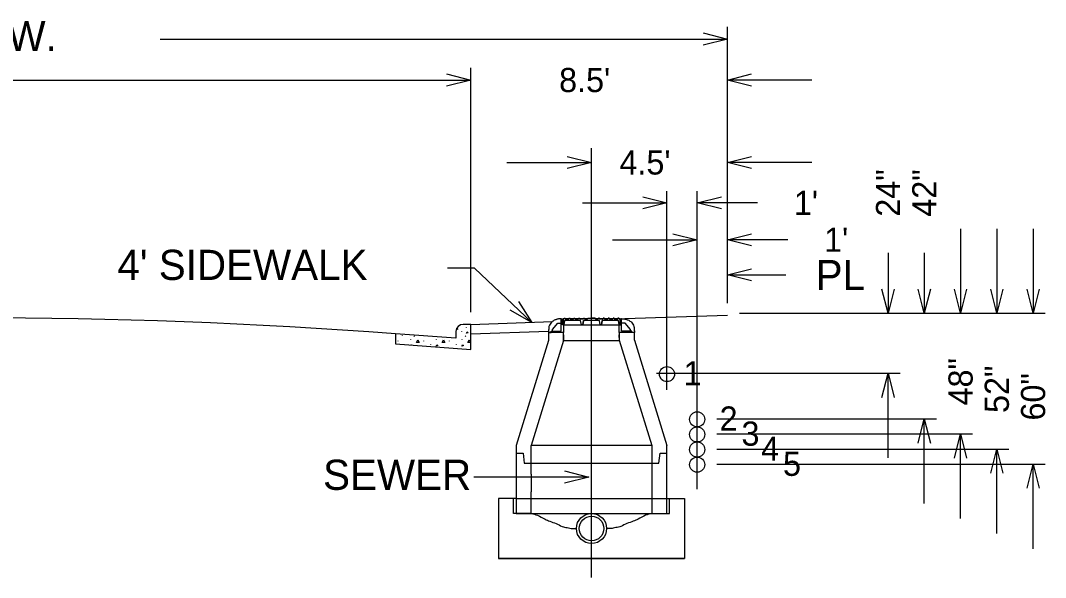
# Model space of a CAD drawing. Extents: x 524397 to 525117, y 3701341 to 3701821.
# Drawn here: x 524790.7 to 524858.6, y 3701583.9 to 3701620.9 of the extents above; entities that cross this region are included whole.
import ezdxf

# ---------------------------------------------------------------- set-up
doc = ezdxf.new("R2010")
doc.units = 0
doc.layers.add('Level 11', color=7, linetype='Continuous')

msp = doc.modelspace()

# ---------------------------------------------------------------- linework, layer by layer
at = {"layer": 'Level 11'}
for p, q in [((524835.918, 3701620.031), (524837.519, 3701619.631)), ((524837.519, 3701602.111), (524837.519, 3701620.431)), ((524799.959, 3701619.631), (524837.519, 3701619.631)), ((524837.519, 3701619.631), (524835.918, 3701619.23)), ((524818.923, 3701617.313), (524820.524, 3701616.913)), ((524818.923, 3701617.313), (524820.524, 3701616.913)), ((524820.524, 3701601.517), (524820.524, 3701617.714)), ((524837.519, 3701602.111), (524837.519, 3701617.714)), ((524837.519, 3701616.913), (524839.12, 3701617.313)), ((524790.181, 3701616.913), (524820.524, 3701616.913)), ((524814.921, 3701616.913), (524820.524, 3701616.913)), ((524820.524, 3701616.913), (524818.923, 3701616.513)), ((524820.524, 3701616.913), (524818.923, 3701616.513)), ((524843.123, 3701616.913), (524837.519, 3701616.913)), ((524839.12, 3701616.513), (524837.519, 3701616.913)), ((524828.519, 3701583.937), (524828.519, 3701612.406)), ((524826.918, 3701611.85), (524828.519, 3701611.45)), ((524837.519, 3701611.45), (524839.12, 3701611.85)), ((524822.916, 3701611.45), (524828.519, 3701611.45)), ((524828.519, 3701611.45), (524826.918, 3701611.05)), ((524843.123, 3701611.45), (524837.519, 3701611.45)), ((524839.12, 3701611.05), (524837.519, 3701611.45)), ((524831.918, 3701609.17), (524833.519, 3701608.77)), ((524833.519, 3701596.371), (524833.519, 3701609.547)), ((524835.519, 3701589.784), (524835.519, 3701609.547)), ((524835.519, 3701608.77), (524837.12, 3701609.17)), ((524827.916, 3701608.77), (524833.519, 3701608.77)), ((524833.519, 3701608.77), (524831.918, 3701608.37)), ((524839.522, 3701608.77), (524835.519, 3701608.77)), ((524837.12, 3701608.37), (524835.519, 3701608.77)), ((524852.962, 3701607.053), (524852.962, 3701601.45)), ((524855.363, 3701607.053), (524855.363, 3701601.45)), ((524857.765, 3701607.053), (524857.765, 3701601.45)), ((524829.916, 3701606.328), (524835.519, 3701606.328)), ((524833.918, 3701606.728), (524835.519, 3701606.328)), ((524835.519, 3701606.328), (524833.918, 3701605.928)), ((524837.519, 3701606.328), (524839.12, 3701606.728)), ((524841.522, 3701606.328), (524837.519, 3701606.328)), ((524839.12, 3701605.928), (524837.519, 3701606.328)), ((524848.159, 3701605.452), (524848.159, 3701601.45)), ((524850.561, 3701605.452), (524850.561, 3701601.45)), ((524820.782, 3701604.452), (524818.977, 3701604.452)), ((524824.56, 3701600.841), (524820.782, 3701604.452)), ((524837.519, 3701604.003), (524839.12, 3701604.403)), ((524837.519, 3701604.003), (524841.395, 3701604.003)), ((524839.12, 3701603.603), (524837.519, 3701604.003)), ((524848.159, 3701601.45), (524847.759, 3701603.051)), ((524848.559, 3701603.051), (524848.159, 3701601.45)), ((524850.561, 3701601.45), (524850.16, 3701603.051)), ((524850.961, 3701603.051), (524850.561, 3701601.45)), ((524852.962, 3701601.45), (524852.562, 3701603.051)), ((524853.362, 3701603.051), (524852.962, 3701601.45)), ((524855.363, 3701601.45), (524854.963, 3701603.051)), ((524855.764, 3701603.051), (524855.363, 3701601.45)), ((524857.765, 3701601.45), (524857.365, 3701603.051)), ((524858.165, 3701603.051), (524857.765, 3701601.45)), ((524823.679, 3701602.236), (524824.56, 3701600.841)), ((524824.56, 3701600.841), (524823.126, 3701601.657)), ((524820.524, 3701600.717), (524825.933, 3701600.906)), ((524826.521, 3701601.094), (524826.521, 3701601.094)), ((524826.521, 3701601.094), (524826.604, 3701601.094)), ((524826.521, 3701600.803), (524826.521, 3701601.094)), ((524826.604, 3701600.678), (524826.604, 3701601.094)), ((524826.646, 3701601.094), (524826.646, 3701600.678)), ((524826.688, 3701601.094), (524826.646, 3701601.094)), ((524826.646, 3701601.094), (524826.688, 3701601.094)), ((524826.646, 3701600.678), (524826.646, 3701601.094)), ((524826.687, 3701600.678), (524826.739, 3701600.969)), ((524826.739, 3701600.969), (524826.687, 3701600.678)), ((524826.688, 3701601.094), (524826.703, 3701601.136)), ((524826.688, 3701601.094), (524826.703, 3701601.136)), ((524826.703, 3701601.136), (524826.766, 3701601.136)), ((524826.703, 3701601.136), (524826.766, 3701601.136)), ((524827.802, 3701600.969), (524826.739, 3701600.969)), ((524827.802, 3701600.969), (524826.739, 3701600.969)), ((524826.781, 3701601.094), (524826.766, 3701601.136)), ((524826.766, 3701601.136), (524826.781, 3701601.094)), ((524827.012, 3701601.094), (524826.781, 3701601.094)), ((524826.781, 3701601.094), (524827.012, 3701601.094)), ((524827.012, 3701601.094), (524827.027, 3701601.136)), ((524827.012, 3701601.094), (524827.027, 3701601.136)), ((524827.027, 3701601.136), (524827.087, 3701601.136)), ((524827.027, 3701601.136), (524827.087, 3701601.136)), ((524827.102, 3701601.094), (524827.087, 3701601.136)), ((524827.087, 3701601.136), (524827.102, 3701601.094)), ((524827.328, 3701601.094), (524827.102, 3701601.094)), ((524827.102, 3701601.094), (524827.328, 3701601.094)), ((524827.328, 3701601.094), (524827.343, 3701601.136)), ((524827.328, 3701601.094), (524827.343, 3701601.136)), ((524827.343, 3701601.136), (524827.411, 3701601.136)), ((524827.343, 3701601.136), (524827.411, 3701601.136)), ((524827.426, 3701601.094), (524827.411, 3701601.136)), ((524827.411, 3701601.136), (524827.426, 3701601.094)), ((524827.655, 3701601.094), (524827.426, 3701601.094)), ((524827.426, 3701601.094), (524827.655, 3701601.094)), ((524827.655, 3701601.094), (524827.671, 3701601.136)), ((524827.655, 3701601.094), (524827.671, 3701601.136)), ((524827.671, 3701601.136), (524827.736, 3701601.136)), ((524827.671, 3701601.136), (524827.736, 3701601.136)), ((524827.751, 3701601.094), (524827.736, 3701601.136)), ((524827.736, 3701601.136), (524827.751, 3701601.094)), ((524827.978, 3701601.094), (524827.751, 3701601.094)), ((524827.751, 3701601.094), (524827.978, 3701601.094)), ((524827.853, 3701600.678), (524827.802, 3701600.969)), ((524827.853, 3701600.678), (524827.802, 3701600.969)), ((524827.937, 3701600.678), (524827.988, 3701600.969)), ((524827.988, 3701600.969), (524827.937, 3701600.678)), ((524827.978, 3701601.094), (524827.993, 3701601.136)), ((524827.978, 3701601.094), (524827.993, 3701601.136)), ((524829.051, 3701600.969), (524827.988, 3701600.969)), ((524829.051, 3701600.969), (524827.988, 3701600.969)), ((524827.993, 3701601.136), (524828.051, 3701601.136)), ((524827.993, 3701601.136), (524828.051, 3701601.136)), ((524828.067, 3701601.094), (524828.051, 3701601.136)), ((524828.051, 3701601.136), (524828.067, 3701601.094)), ((524828.253, 3701601.094), (524828.067, 3701601.094)), ((524828.067, 3701601.094), (524828.253, 3701601.094)), ((524828.253, 3701601.094), (524828.269, 3701601.136)), ((524828.253, 3701601.094), (524828.269, 3701601.136)), ((524828.269, 3701601.136), (524828.519, 3701601.136)), ((524828.269, 3701601.136), (524828.771, 3701601.136)), ((524828.771, 3701601.136), (524828.519, 3701601.136)), ((524828.786, 3701601.094), (524828.771, 3701601.136)), ((524828.771, 3701601.136), (524828.786, 3701601.094)), ((524828.973, 3701601.094), (524828.786, 3701601.094)), ((524828.786, 3701601.094), (524828.973, 3701601.094)), ((524828.973, 3701601.094), (524828.988, 3701601.136)), ((524828.973, 3701601.094), (524828.988, 3701601.136)), ((524829.046, 3701601.136), (524828.988, 3701601.136)), ((524828.988, 3701601.136), (524829.046, 3701601.136)), ((524829.061, 3701601.094), (524829.046, 3701601.136)), ((524829.046, 3701601.136), (524829.061, 3701601.094)), ((524829.103, 3701600.678), (524829.051, 3701600.969)), ((524829.103, 3701600.678), (524829.051, 3701600.969)), ((524829.288, 3701601.094), (524829.061, 3701601.094)), ((524829.061, 3701601.094), (524829.288, 3701601.094)), ((524829.186, 3701600.678), (524829.237, 3701600.969)), ((524829.237, 3701600.969), (524829.186, 3701600.678)), ((524830.3, 3701600.969), (524829.237, 3701600.969)), ((524830.081, 3701600.969), (524829.237, 3701600.969)), ((524829.288, 3701601.094), (524829.304, 3701601.136)), ((524829.288, 3701601.094), (524829.304, 3701601.136)), ((524829.369, 3701601.136), (524829.304, 3701601.136)), ((524829.304, 3701601.136), (524829.369, 3701601.136)), ((524829.384, 3701601.094), (524829.369, 3701601.136)), ((524829.369, 3701601.136), (524829.384, 3701601.094)), ((524829.613, 3701601.094), (524829.384, 3701601.094)), ((524829.384, 3701601.094), (524829.613, 3701601.094)), ((524829.613, 3701601.094), (524829.628, 3701601.136)), ((524829.613, 3701601.094), (524829.628, 3701601.136)), ((524829.696, 3701601.136), (524829.628, 3701601.136)), ((524829.628, 3701601.136), (524829.696, 3701601.136)), ((524829.711, 3701601.094), (524829.696, 3701601.136)), ((524829.696, 3701601.136), (524829.711, 3701601.094)), ((524829.938, 3701601.094), (524829.711, 3701601.094)), ((524829.711, 3701601.094), (524829.938, 3701601.094)), ((524829.938, 3701601.094), (524829.952, 3701601.136)), ((524829.938, 3701601.094), (524829.952, 3701601.136)), ((524830.012, 3701601.136), (524829.952, 3701601.136)), ((524829.952, 3701601.136), (524830.012, 3701601.136)), ((524830.027, 3701601.094), (524830.012, 3701601.136)), ((524830.012, 3701601.136), (524830.027, 3701601.094)), ((524830.258, 3701601.094), (524830.027, 3701601.094)), ((524830.027, 3701601.094), (524830.081, 3701601.094)), ((524830.081, 3701601.094), (524830.081, 3701600.969)), ((524830.081, 3701601.094), (524830.081, 3701600.969)), ((524830.206, 3701601.094), (524830.206, 3701600.969)), ((524830.206, 3701601.094), (524830.258, 3701601.094)), ((524830.206, 3701600.969), (524830.206, 3701601.094)), ((524830.3, 3701600.969), (524830.206, 3701600.969)), ((524830.258, 3701601.094), (524830.274, 3701601.136)), ((524830.258, 3701601.094), (524830.274, 3701601.136)), ((524830.336, 3701601.136), (524830.274, 3701601.136)), ((524830.274, 3701601.136), (524830.336, 3701601.136)), ((524830.352, 3701600.678), (524830.3, 3701600.969)), ((524830.352, 3701600.678), (524830.3, 3701600.969)), ((524830.351, 3701601.094), (524830.336, 3701601.136)), ((524830.336, 3701601.136), (524830.351, 3701601.094)), ((524830.393, 3701601.094), (524830.351, 3701601.094)), ((524830.351, 3701601.094), (524830.393, 3701601.094)), ((524830.393, 3701601.094), (524830.393, 3701600.678)), ((524830.393, 3701601.094), (524830.393, 3701600.678)), ((524830.435, 3701600.678), (524830.435, 3701601.094)), ((524830.518, 3701601.094), (524830.435, 3701601.094)), ((524830.518, 3701600.803), (524830.518, 3701601.094)), ((524837.519, 3701601.31), (524830.726, 3701601.073)), ((524838.32, 3701601.45), (524848.96, 3701601.45)), ((524838.32, 3701601.45), (524851.361, 3701601.45)), ((524838.32, 3701601.45), (524853.762, 3701601.45)), ((524838.32, 3701601.45), (524856.164, 3701601.45)), ((524838.32, 3701601.45), (524858.565, 3701601.45)), ((524819.53, 3701600.254), (524819.53, 3701599.792)), ((524819.919, 3701600.268), (524819.922, 3701600.237)), ((524820.53, 3701600.717), (524820.017, 3701600.717)), ((524820.017, 3701600.717), (524820.03, 3701600.717)), ((524820.236, 3701600.503), (524820.25, 3701600.535)), ((524820.524, 3701600.057), (524820.524, 3701600.717)), ((524825.68, 3701600.237), (524820.524, 3701600.057)), ((524820.53, 3701599.055), (524820.53, 3701600.717)), ((524825.677, 3701600.178), (524825.677, 3701599.645)), ((524826.687, 3701600.178), (524825.677, 3701600.178)), ((524825.677, 3701600.178), (524825.854, 3701600.178)), ((524825.854, 3701600.178), (524825.854, 3701600.261)), ((524825.854, 3701600.261), (524825.938, 3701600.261)), ((524825.938, 3701600.366), (524826.288, 3701600.803)), ((524825.938, 3701600.261), (524825.938, 3701600.366)), ((524825.938, 3701600.261), (524826.521, 3701600.261)), ((524826.288, 3701600.803), (524826.521, 3701600.803)), ((524826.521, 3701600.261), (524826.521, 3701600.803)), ((524826.687, 3701600.678), (524826.604, 3701600.678)), ((524826.646, 3701600.678), (524830.393, 3701600.678)), ((524826.687, 3701600.678), (524826.646, 3701600.678)), ((524826.677, 3701599.645), (524826.677, 3701600.178)), ((524826.687, 3701600.178), (524826.687, 3701600.678)), ((524827.937, 3701600.678), (524827.853, 3701600.678)), ((524829.186, 3701600.678), (524829.103, 3701600.678)), ((524830.352, 3701600.178), (524830.352, 3701600.678)), ((524830.352, 3701600.678), (524830.435, 3701600.678)), ((524830.393, 3701600.678), (524830.352, 3701600.678)), ((524831.362, 3701600.178), (524830.352, 3701600.178)), ((524830.362, 3701600.178), (524830.362, 3701599.678)), ((524831.362, 3701600.178), (524830.363, 3701600.178)), ((524830.518, 3701600.261), (524830.518, 3701600.803)), ((524830.751, 3701600.803), (524830.518, 3701600.803)), ((524831.101, 3701600.261), (524830.518, 3701600.261)), ((524831.101, 3701600.366), (524830.751, 3701600.803)), ((524831.101, 3701600.261), (524831.101, 3701600.366)), ((524831.184, 3701600.261), (524831.101, 3701600.261)), ((524831.184, 3701600.178), (524831.184, 3701600.261)), ((524831.362, 3701600.178), (524831.184, 3701600.178)), ((524831.362, 3701599.678), (524831.362, 3701600.178)), ((524819.53, 3701599.792), (524815.53, 3701600.094)), ((524815.53, 3701600.094), (524815.53, 3701599.432)), ((524815.707, 3701599.601), (524815.721, 3701599.633)), ((524815.995, 3701599.946), (524816.009, 3701599.978)), ((524816.549, 3701599.682), (524816.563, 3701599.714)), ((524816.758, 3701599.946), (524816.773, 3701599.924)), ((524816.773, 3701599.938), (524816.787, 3701599.916)), ((524817.408, 3701599.601), (524817.423, 3701599.633)), ((524818.25, 3701599.682), (524818.264, 3701599.714)), ((524819.11, 3701599.601), (524819.124, 3701599.633)), ((524819.952, 3701599.682), (524819.966, 3701599.714)), ((524820.161, 3701599.946), (524820.176, 3701599.924)), ((524820.176, 3701599.938), (524820.19, 3701599.916)), ((524825.677, 3701599.645), (524823.527, 3701592.678)), ((524826.677, 3701599.645), (524824.526, 3701592.678)), ((524826.677, 3701600.012), (524826.677, 3701599.685)), ((524826.677, 3701599.645), (524830.362, 3701599.645)), ((524830.362, 3701599.845), (524830.362, 3701600.018)), ((524830.362, 3701599.678), (524832.522, 3701592.683)), ((524831.362, 3701599.678), (524833.521, 3701592.683)), ((524815.53, 3701599.432), (524820.53, 3701599.055)), ((524817.852, 3701599.373), (524817.867, 3701599.352)), ((524819.554, 3701599.373), (524819.568, 3701599.352)), ((524832.82, 3701597.478), (524848.96, 3701597.478)), ((524847.759, 3701595.877), (524848.159, 3701597.478)), ((524848.159, 3701591.875), (524848.159, 3701597.478)), ((524848.159, 3701597.478), (524848.559, 3701595.877)), ((524836.82, 3701594.45), (524851.361, 3701594.45)), ((524850.16, 3701592.849), (524850.561, 3701594.45)), ((524850.561, 3701588.846), (524850.561, 3701594.45)), ((524850.561, 3701594.45), (524850.961, 3701592.849)), ((524836.82, 3701593.45), (524853.762, 3701593.45)), ((524852.562, 3701591.849), (524852.962, 3701593.45)), ((524852.962, 3701587.846), (524852.962, 3701593.45)), ((524852.962, 3701593.45), (524853.362, 3701591.849)), ((524823.527, 3701592.678), (524823.527, 3701591.517)), ((524823.527, 3701592.385), (524823.527, 3701592.183)), ((524823.527, 3701592.183), (524823.985, 3701592.183)), ((524823.527, 3701592.183), (524823.985, 3701592.183)), ((524823.527, 3701592.183), (524823.527, 3701590.795)), ((524823.985, 3701592.183), (524824.068, 3701591.517)), ((524823.985, 3701592.183), (524824.068, 3701591.517)), ((524832.522, 3701592.682), (524824.526, 3701592.678)), ((524824.526, 3701591.517), (524824.526, 3701592.678)), ((524824.526, 3701592.183), (524824.526, 3701592.385)), ((524824.526, 3701590.795), (524824.526, 3701592.183)), ((524832.522, 3701592.683), (524832.522, 3701591.517)), ((524832.522, 3701592.683), (524832.522, 3701592.183)), ((524832.522, 3701592.385), (524832.522, 3701592.183)), ((524832.522, 3701592.385), (524832.522, 3701592.183)), ((524832.522, 3701592.183), (524832.522, 3701588.185)), ((524832.522, 3701592.183), (524832.522, 3701588.185)), ((524832.98, 3701591.517), (524833.063, 3701592.183)), ((524832.98, 3701591.517), (524833.063, 3701592.183)), ((524833.063, 3701592.183), (524833.521, 3701592.183)), ((524833.063, 3701592.183), (524833.521, 3701592.183)), ((524833.063, 3701592.183), (524833.521, 3701592.183)), ((524833.521, 3701592.183), (524833.521, 3701592.683)), ((524833.521, 3701592.183), (524833.521, 3701592.683)), ((524833.521, 3701588.185), (524833.521, 3701592.385)), ((524833.521, 3701591.517), (524833.521, 3701592.183)), ((524836.82, 3701592.45), (524856.164, 3701592.45)), ((524854.963, 3701590.849), (524855.363, 3701592.45)), ((524855.363, 3701586.846), (524855.363, 3701592.45)), ((524855.363, 3701592.45), (524855.764, 3701590.849)), ((524823.527, 3701591.795), (524823.527, 3701588.185)), ((524824.068, 3701591.517), (524824.526, 3701591.517)), ((524824.068, 3701591.517), (524824.526, 3701591.517)), ((524824.526, 3701591.517), (524832.522, 3701591.517)), ((524824.526, 3701591.517), (524832.522, 3701591.517)), ((524832.522, 3701591.517), (524832.98, 3701591.517)), ((524832.522, 3701591.517), (524832.98, 3701591.517)), ((524836.82, 3701591.45), (524858.565, 3701591.45)), ((524857.365, 3701589.849), (524857.765, 3701591.45)), ((524857.765, 3701585.846), (524857.765, 3701591.45)), ((524857.765, 3701591.45), (524858.165, 3701589.849)), ((524824.526, 3701590.795), (524824.526, 3701589.611)), ((524826.734, 3701590.999), (524828.335, 3701590.599)), ((524828.335, 3701590.599), (524820.718, 3701590.599)), ((524828.335, 3701590.599), (524826.734, 3701590.199)), ((524824.526, 3701588.185), (524824.526, 3701589.611)), ((524823.527, 3701589.185), (524822.361, 3701589.185)), ((524822.361, 3701589.185), (524822.361, 3701585.187)), ((524823.361, 3701588.185), (524823.361, 3701589.185)), ((524823.527, 3701589.185), (524833.521, 3701589.185)), ((524833.521, 3701589.185), (524834.687, 3701589.185)), ((524833.688, 3701588.185), (524833.688, 3701589.185)), ((524834.687, 3701589.185), (524834.687, 3701585.187)), ((524823.527, 3701588.185), (524823.361, 3701588.185)), ((524823.527, 3701588.185), (524823.361, 3701588.185)), ((524823.527, 3701588.185), (524824.526, 3701588.185)), ((524824.526, 3701588.185), (524823.527, 3701588.185)), ((524824.526, 3701588.185), (524823.527, 3701588.185)), ((524824.526, 3701588.185), (524832.522, 3701588.185)), ((524832.522, 3701588.185), (524833.521, 3701588.185)), ((524832.522, 3701588.185), (524833.521, 3701588.185)), ((524833.521, 3701588.185), (524833.688, 3701588.185)), ((524834.687, 3701585.187), (524822.361, 3701585.187)), ((524822.361, 3701585.187), (524834.687, 3701585.187))]:
    msp.add_line(p, q, dxfattribs=at)
for points in [[(524819.594, 3701600.463), (524819.662, 3701600.393), (524819.558, 3701600.344)], [(524820.243, 3701600.13), (524820.286, 3701600.219), (524820.357, 3701600.166), (524820.243, 3701600.13)], [(524816.929, 3701599.505), (524817.025, 3701599.686), (524817.099, 3701599.519), (524816.932, 3701599.505)], [(524818.63, 3701599.505), (524818.726, 3701599.686), (524818.801, 3701599.519), (524818.634, 3701599.505)], [(524820.332, 3701599.505), (524820.428, 3701599.686), (524820.502, 3701599.519), (524820.335, 3701599.505)], [(524816.559, 3701599.355), (524816.566, 3701599.37), (524816.59, 3701599.352)], [(524818.225, 3701599.281), (524818.268, 3701599.37), (524818.339, 3701599.316), (524818.225, 3701599.281)], [(524819.927, 3701599.281), (524819.969, 3701599.37), (524820.04, 3701599.316), (524819.927, 3701599.281)]]:
    msp.add_lwpolyline(points, dxfattribs=at)
for centre, radius in [((524833.519, 3701597.42), 0.5), ((524835.519, 3701594.42), 0.5), ((524835.519, 3701593.42), 0.5), ((524835.519, 3701592.42), 0.5), ((524835.519, 3701591.42), 0.5), ((524828.524, 3701587.186), 0.999), ((524828.524, 3701587.186), 0.814)]:
    msp.add_circle(centre, radius, dxfattribs=at)
for centre, radius, start, end in [((524787.525, 3701229.225), 371.925, 85.68167, 94.31764), ((524820.023, 3701600.222), 0.494, 89.23325, 176.29205)]:
    msp.add_arc(centre, radius, start, end, dxfattribs=at)
for points in [[(524826.521, 3701601.094), (524826.448, 3701601.093), (524826.369, 3701601.083), (524826.3, 3701601.071), (524826.241, 3701601.059), (524826.177, 3701601.031), (524826.119, 3701601.017), (524825.976, 3701600.938), (524825.872, 3701600.852), (524825.781, 3701600.734), (524825.705, 3701600.57), (524825.684, 3701600.337), (524825.677, 3701600.178)], [(524830.518, 3701601.094), (524830.591, 3701601.093), (524830.67, 3701601.083), (524830.739, 3701601.071), (524830.798, 3701601.059), (524830.862, 3701601.031), (524830.921, 3701601.017), (524831.064, 3701600.938), (524831.167, 3701600.852), (524831.258, 3701600.734), (524831.334, 3701600.57), (524831.355, 3701600.337), (524831.362, 3701600.178)], [(524824.526, 3701588.185), (524824.941, 3701588.061), (524825.444, 3701587.809), (524825.759, 3701587.662), (524826.179, 3701587.516), (524826.578, 3701587.327), (524826.914, 3701587.243), (524827.25, 3701587.18), (524827.525, 3701587.186)], [(524832.522, 3701588.185), (524832.108, 3701588.061), (524831.604, 3701587.809), (524831.289, 3701587.662), (524830.869, 3701587.516), (524830.47, 3701587.327), (524830.134, 3701587.243), (524829.798, 3701587.18), (524829.523, 3701587.186)]]:
    msp.add_spline(points, degree=3, dxfattribs=at)

# ---------------------------------------------------------------- texts
for s, height, p in [("50' R.O.W.", 2, (524780.118, 3701618.829)), ("8.5'", 1.601, (524826.375, 3701616.112)), ("4.5'", 1.601, (524830.372, 3701610.648)), ("1'", 1.601, (524841.924, 3701607.968)), ("1'", 1.601, (524843.924, 3701605.526)), ("4' SIDEWALK", 2, (524797.122, 3701603.661)), ('PL', 2, (524843.366, 3701602.985)), ('1', 1.601, (524834.623, 3701596.675)), ('2', 1.601, (524837.005, 3701593.675)), ('3', 1.601, (524838.455, 3701592.675)), ('4', 1.601, (524839.754, 3701591.675)), ('5', 1.601, (524841.204, 3701590.675)), ('SEWER', 2, (524810.743, 3701589.748))]:
    msp.add_text(s, height=height, dxfattribs=at).set_placement(p)
for s, p in [('24"', (524848.96, 3701607.852)), ('42"', (524851.361, 3701607.852)), ('48"', (524853.763, 3701595.343)), ('52"', (524856.164, 3701594.843)), ('60"', (524858.565, 3701594.343))]:
    msp.add_text(s, height=1.601, rotation=90, dxfattribs=at).set_placement(p)

doc.saveas('drawing.dxf')
